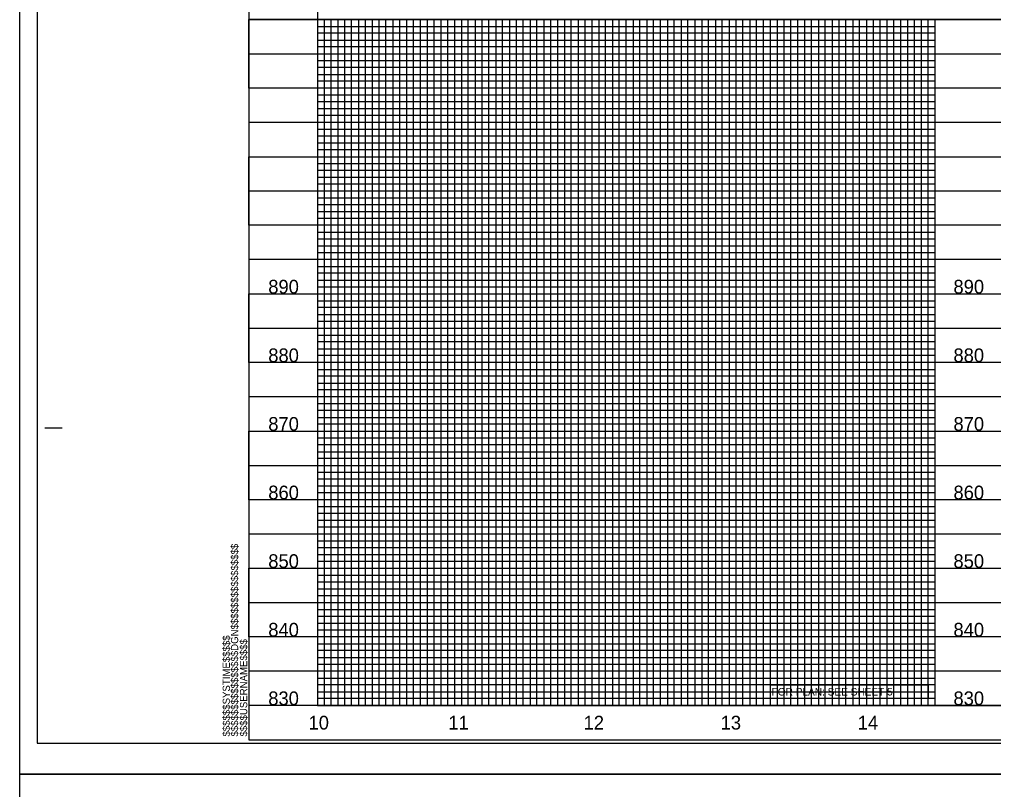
# Model space of a CAD drawing. Extents: x 1967929 to 1975641, y 546296 to 568534.
# Drawn here: x 1969864 to 1970574, y 566323 to 566884 of the extents above; entities that cross this region are included whole.
import ezdxf

# ---------------------------------------------------------------- set-up
doc = ezdxf.new("R2010")
doc.units = 0
for name, color, linetype in [('Exist Vertical Profile Horizontal Axis Label Major', 7, 'Continuous'), ('Exist Vertical Profile Vertical Axis Label', 7, 'Continuous'), ('Old_Level_41', 7, 'Continuous'), ('Old_Level_42', 7, 'Continuous'), ('Prop Grid Mask', 7, 'Continuous'), ('Scratch_Level_3', 7, 'Continuous'), ('Sheet Cutting Line CELL', 7, 'Continuous'), ('Sheet Plot Border Inside CELL', 7, 'Continuous'), ('Sheet Plot Border Outside CELL', 7, 'Continuous'), ('Sheet Profile CELL', 7, 'Continuous'), ('Sheet Profile Grid Major CELL', 7, 'Continuous'), ('Sheet Profile Grid Middle CELL', 7, 'Continuous'), ('Sheet Profile Grid Minor CELL', 7, 'Continuous')]:
    doc.layers.add(name, color=color, linetype=linetype)

msp = doc.modelspace()

# ---------------------------------------------------------------- linework, layer by layer
at = {"layer": 'Old_Level_41'}
msp.add_line((1969882.95, 566586.36), (1969895.45, 566586.36), dxfattribs=at)
at = {"layer": 'Old_Level_42'}
msp.add_line((1970031.45, 566383.86), (1970031.45, 566383.86), dxfattribs=at)
at = {"layer": 'Prop Grid Mask'}
msp.add_lwpolyline([(1970411.53, 566398.9), (1970526.41, 566398.9), (1970526.41, 566388.87), (1970411.53, 566388.87)], close=True, dxfattribs=at)
at = {"layer": 'Scratch_Level_3'}
for points in [[(1970081.45, 566983.86), (1970081.45, 566483.86), (1970581.45, 566483.86), (1970581.45, 566683.86), (1970581.45, 566803.86), (1970581.45, 566983.86)], [(1970081.45, 566883.86), (1970081.45, 566383.86), (1971481.45, 566383.86), (1971481.45, 566883.86)], [(1970081.45, 566883.86), (1970081.45, 566383.86), (1971381.45, 566383.86), (1971381.45, 566883.86)], [(1970081.45, 566883.86), (1970081.45, 566383.86), (1971481.45, 566383.86), (1971481.45, 566883.86)]]:
    msp.add_lwpolyline(points, close=True, dxfattribs=at)
at = {"layer": 'Sheet Cutting Line CELL'}
for p, q in [((1969864.45, 567433.86), (1969864.45, 566333.86)), ((1969864.45, 566333.86), (1971548.45, 566333.86)), ((1969864.45, 566333.86), (1969864.45, 565233.86))]:
    msp.add_line(p, q, dxfattribs=at)
at = {"layer": 'Sheet Plot Border Inside CELL'}
msp.add_lwpolyline([(1969877.45, 566356.31), (1971543.95, 566356.31), (1971543.95, 567411.41), (1969877.45, 567411.41)], close=True, dxfattribs=at)
at = {"layer": 'Sheet Plot Border Outside CELL'}
for points in [[(1969864.45, 566333.86), (1971548.45, 566333.86), (1971548.45, 567433.86), (1969864.45, 567433.86)], [(1969864.45, 565233.86), (1971548.45, 565233.86), (1971548.45, 566333.86), (1969864.45, 566333.86)]]:
    msp.add_lwpolyline(points, close=True, dxfattribs=at)
at = {"layer": 'Sheet Profile CELL'}
for p, q in [((1971531.45, 566883.86), (1970031.45, 566883.86)), ((1971531.45, 566383.86), (1970031.45, 566383.86))]:
    msp.add_line(p, q, dxfattribs=at)
msp.add_lwpolyline([(1971531.45, 567408.86), (1970031.45, 567408.86), (1970031.45, 566358.86), (1971531.45, 566358.86)], close=True, dxfattribs=at)
at = {"layer": 'Sheet Profile Grid Major CELL'}
for points in [[(1971531.45, 566833.86), (1970031.45, 566833.86), (1970031.45, 566883.86), (1971531.45, 566883.86)], [(1970081.45, 566883.86), (1970081.45, 566383.86), (1970131.45, 566383.86), (1970131.45, 566883.86)], [(1970181.45, 566883.86), (1970181.45, 566383.86), (1970231.45, 566383.86), (1970231.45, 566883.86)], [(1970281.45, 566883.86), (1970281.45, 566383.86), (1970331.45, 566383.86), (1970331.45, 566883.86)], [(1970381.45, 566883.86), (1970381.45, 566383.86), (1970431.45, 566383.86), (1970431.45, 566883.86)], [(1970481.45, 566883.86), (1970481.45, 566383.86), (1970531.45, 566383.86), (1970531.45, 566883.86)], [(1971531.45, 566733.86), (1970031.45, 566733.86), (1970031.45, 566783.86), (1971531.45, 566783.86)], [(1971531.45, 566633.86), (1970031.45, 566633.86), (1970031.45, 566683.86), (1971531.45, 566683.86)], [(1971531.45, 566533.86), (1970031.45, 566533.86), (1970031.45, 566583.86), (1971531.45, 566583.86)], [(1971531.45, 566433.86), (1970031.45, 566433.86), (1970031.45, 566483.86), (1971531.45, 566483.86)]]:
    msp.add_lwpolyline(points, dxfattribs=at)
at = {"layer": 'Sheet Profile Grid Middle CELL'}
for points in [[(1970031.45, 566883.86), (1970031.45, 566858.86), (1971531.45, 566858.86)], [(1970106.45, 566383.86), (1970106.45, 566883.86)], [(1970156.45, 566883.86), (1970156.45, 566383.86), (1970206.45, 566383.86), (1970206.45, 566883.86)], [(1970256.45, 566883.86), (1970256.45, 566383.86), (1970306.45, 566383.86), (1970306.45, 566883.86)], [(1970356.45, 566883.86), (1970356.45, 566383.86), (1970406.45, 566383.86), (1970406.45, 566883.86)], [(1970456.45, 566883.86), (1970456.45, 566383.86), (1970506.45, 566383.86), (1970506.45, 566883.86)], [(1971531.45, 566808.86), (1970031.45, 566808.86), (1970031.45, 566758.86), (1971531.45, 566758.86)], [(1971531.45, 566708.86), (1970031.45, 566708.86), (1970031.45, 566658.86), (1971531.45, 566658.86)], [(1971531.45, 566608.86), (1970031.45, 566608.86), (1970031.45, 566558.86), (1971531.45, 566558.86)], [(1971531.45, 566508.86), (1970031.45, 566508.86), (1970031.45, 566458.86), (1971531.45, 566458.86)], [(1971531.45, 566408.86), (1970031.45, 566408.86)]]:
    msp.add_lwpolyline(points, dxfattribs=at)
at = {"layer": 'Sheet Profile Grid Minor CELL'}
for points in [[(1970086.45, 566883.86), (1970086.45, 566383.86), (1970091.45, 566383.86), (1970091.45, 566883.86)], [(1970096.45, 566883.86), (1970096.45, 566383.86), (1970101.45, 566383.86), (1970101.45, 566883.86)], [(1970111.45, 566883.86), (1970111.45, 566383.86), (1970116.45, 566383.86), (1970116.45, 566883.86)], [(1970121.45, 566883.86), (1970121.45, 566383.86), (1970126.45, 566383.86), (1970126.45, 566883.86)], [(1970136.45, 566883.86), (1970136.45, 566383.86), (1970141.45, 566383.86), (1970141.45, 566883.86)], [(1970146.45, 566883.86), (1970146.45, 566383.86), (1970151.45, 566383.86), (1970151.45, 566883.86)], [(1970161.45, 566883.86), (1970161.45, 566383.86), (1970166.45, 566383.86), (1970166.45, 566883.86)], [(1970171.45, 566883.86), (1970171.45, 566383.86), (1970176.45, 566383.86), (1970176.45, 566883.86)], [(1970186.45, 566883.86), (1970186.45, 566383.86), (1970191.45, 566383.86), (1970191.45, 566883.86)], [(1970196.45, 566883.86), (1970196.45, 566383.86), (1970201.45, 566383.86), (1970201.45, 566883.86)], [(1970211.45, 566883.86), (1970211.45, 566383.86), (1970216.45, 566383.86), (1970216.45, 566883.86)], [(1970221.45, 566883.86), (1970221.45, 566383.86), (1970226.45, 566383.86), (1970226.45, 566883.86)], [(1970236.45, 566883.86), (1970236.45, 566383.86), (1970241.45, 566383.86), (1970241.45, 566883.86)], [(1970246.45, 566383.86), (1970251.45, 566383.86), (1970251.45, 566883.86)], [(1970246.45, 566883.86), (1970246.45, 566383.86)], [(1970261.45, 566883.86), (1970261.45, 566383.86), (1970266.45, 566383.86), (1970266.45, 566883.86)], [(1970271.45, 566883.86), (1970271.45, 566383.86), (1970276.45, 566383.86), (1970276.45, 566883.86)], [(1970286.45, 566883.86), (1970286.45, 566383.86), (1970291.45, 566383.86), (1970291.45, 566883.86)], [(1970296.45, 566883.86), (1970296.45, 566383.86), (1970301.45, 566383.86), (1970301.45, 566883.86)], [(1970311.45, 566883.86), (1970311.45, 566383.86), (1970316.45, 566383.86), (1970316.45, 566883.86)], [(1970321.45, 566883.86), (1970321.45, 566383.86), (1970326.45, 566383.86), (1970326.45, 566883.86)], [(1970336.45, 566883.86), (1970336.45, 566383.86), (1970341.45, 566383.86), (1970341.45, 566883.86)], [(1970346.45, 566883.86), (1970346.45, 566383.86), (1970351.45, 566383.86), (1970351.45, 566883.86)], [(1970361.45, 566883.86), (1970361.45, 566383.86), (1970366.45, 566383.86), (1970366.45, 566883.86)], [(1970371.45, 566883.86), (1970371.45, 566383.86), (1970376.45, 566383.86), (1970376.45, 566883.86)], [(1970386.45, 566883.86), (1970386.45, 566383.86), (1970391.45, 566383.86), (1970391.45, 566883.86)], [(1970396.45, 566883.86), (1970396.45, 566383.86), (1970401.45, 566383.86), (1970401.45, 566883.86)], [(1970411.45, 566883.86), (1970411.45, 566383.86), (1970426.45, 566383.86), (1970426.45, 566883.86)], [(1970416.45, 566883.86), (1970416.45, 566383.86), (1970421.45, 566383.86), (1970421.45, 566883.86)], [(1970436.45, 566883.86), (1970436.45, 566383.86), (1970441.45, 566383.86), (1970441.45, 566883.86)], [(1970446.45, 566883.86), (1970446.45, 566383.86), (1970451.45, 566383.86), (1970451.45, 566883.86)], [(1970461.45, 566883.86), (1970461.45, 566383.86), (1970466.45, 566383.86), (1970466.45, 566883.86)], [(1970471.45, 566883.86), (1970471.45, 566383.86), (1970476.45, 566383.86), (1970476.45, 566883.86)], [(1970486.45, 566883.86), (1970486.45, 566383.86), (1970491.45, 566383.86), (1970491.45, 566883.86)], [(1970496.45, 566883.86), (1970496.45, 566383.86), (1970501.45, 566383.86), (1970501.45, 566883.86)], [(1970511.45, 566883.86), (1970511.45, 566383.86), (1970516.45, 566383.86), (1970516.45, 566883.86)], [(1970521.45, 566883.86), (1970521.45, 566383.86), (1970526.45, 566383.86), (1970526.45, 566883.86)], [(1970081.45, 566878.86), (1970531.45, 566878.86)], [(1970531.45, 566873.86), (1970081.45, 566873.86), (1970081.45, 566868.86), (1970531.45, 566868.86)], [(1970531.45, 566863.86), (1970081.45, 566863.86), (1970081.45, 566853.86), (1970531.45, 566853.86)], [(1970531.45, 566848.86), (1970081.45, 566848.86), (1970081.45, 566843.86), (1970531.45, 566843.86)], [(1970531.45, 566838.86), (1970081.45, 566838.86), (1970081.45, 566828.86), (1970531.45, 566828.86)], [(1970531.45, 566823.86), (1970081.45, 566823.86), (1970081.45, 566818.86), (1970531.45, 566818.86)], [(1970531.45, 566813.86), (1970081.45, 566813.86), (1970081.45, 566803.86), (1970531.45, 566803.86)], [(1970531.45, 566798.86), (1970081.45, 566798.86), (1970081.45, 566793.86), (1970531.45, 566793.86)], [(1970531.45, 566788.86), (1970081.45, 566788.86), (1970081.45, 566778.86), (1970531.45, 566778.86)], [(1970531.45, 566773.86), (1970081.45, 566773.86), (1970081.45, 566768.86), (1970531.45, 566768.86)], [(1970531.45, 566763.86), (1970081.45, 566763.86), (1970081.45, 566753.86), (1970531.45, 566753.86)], [(1970531.45, 566748.86), (1970081.45, 566748.86), (1970081.45, 566743.86), (1970531.45, 566743.86)], [(1970531.45, 566738.86), (1970081.45, 566738.86), (1970081.45, 566728.86), (1970531.45, 566728.86)], [(1970531.45, 566723.86), (1970081.45, 566723.86), (1970081.45, 566718.86), (1970531.45, 566718.86)], [(1970531.45, 566713.86), (1970081.45, 566713.86), (1970081.45, 566703.86), (1970531.45, 566703.86)], [(1970531.45, 566698.86), (1970081.45, 566698.86), (1970081.45, 566693.86), (1970531.45, 566693.86)], [(1970531.45, 566688.86), (1970081.45, 566688.86), (1970081.45, 566678.86), (1970531.45, 566678.86)], [(1970531.45, 566673.86), (1970081.45, 566673.86), (1970081.45, 566668.86), (1970531.45, 566668.86)], [(1970531.45, 566663.86), (1970081.45, 566663.86), (1970081.45, 566653.86), (1970531.45, 566653.86)], [(1970531.45, 566648.86), (1970081.45, 566648.86), (1970081.45, 566643.86), (1970531.45, 566643.86)], [(1970531.45, 566638.86), (1970081.45, 566638.86), (1970081.45, 566628.86), (1970531.45, 566628.86)], [(1970531.45, 566623.86), (1970081.45, 566623.86), (1970081.45, 566618.86), (1970531.45, 566618.86)], [(1970531.45, 566613.86), (1970081.45, 566613.86), (1970081.45, 566603.86), (1970531.45, 566603.86)], [(1970531.45, 566598.86), (1970081.45, 566598.86), (1970081.45, 566593.86), (1970531.45, 566593.86)], [(1970531.45, 566588.86), (1970081.45, 566588.86)], [(1970081.45, 566578.86), (1970531.45, 566578.86)], [(1970531.45, 566573.86), (1970081.45, 566573.86), (1970081.45, 566568.86), (1970531.45, 566568.86)], [(1970531.45, 566563.86), (1970081.45, 566563.86)], [(1970081.45, 566553.86), (1970531.45, 566553.86)], [(1970531.45, 566548.86), (1970081.45, 566548.86), (1970081.45, 566543.86), (1970531.45, 566543.86)], [(1970531.45, 566538.86), (1970081.45, 566538.86), (1970081.45, 566528.86), (1970531.45, 566528.86)], [(1970531.45, 566523.86), (1970081.45, 566523.86), (1970081.45, 566518.86), (1970531.45, 566518.86)], [(1970531.45, 566513.86), (1970081.45, 566513.86), (1970081.45, 566503.86), (1970531.45, 566503.86)], [(1970531.45, 566498.86), (1970081.45, 566498.86), (1970081.45, 566493.86), (1970531.45, 566493.86)], [(1970531.45, 566488.86), (1970081.45, 566488.86), (1970081.45, 566478.86), (1970531.45, 566478.86)], [(1970531.45, 566473.86), (1970081.45, 566473.86), (1970081.45, 566468.86), (1970531.45, 566468.86)], [(1970531.45, 566463.86), (1970081.45, 566463.86), (1970081.45, 566453.86), (1970531.45, 566453.86)], [(1970531.45, 566448.86), (1970081.45, 566448.86), (1970081.45, 566443.86), (1970531.45, 566443.86)], [(1970531.45, 566438.86), (1970081.45, 566438.86), (1970081.45, 566428.86), (1970531.45, 566428.86)], [(1970531.45, 566423.86), (1970081.45, 566423.86), (1970081.45, 566418.86), (1970531.45, 566418.86)], [(1970531.45, 566413.86), (1970081.45, 566413.86), (1970081.45, 566403.86), (1970531.45, 566403.86)], [(1970531.45, 566398.86), (1970081.45, 566398.86), (1970081.45, 566393.86), (1970531.45, 566393.86)], [(1970531.45, 566388.86), (1970081.45, 566388.86), (1970081.45, 566383.86), (1971481.45, 566383.86)]]:
    msp.add_lwpolyline(points, dxfattribs=at)

# ---------------------------------------------------------------- texts
at = {"layer": 'Exist Vertical Profile Horizontal Axis Label Major'}
for s, p in [('10', (1970075.03, 566366.36)), ('11', (1970176.87, 566366.36)), ('12', (1970275.42, 566366.36)), ('13', (1970375.26, 566366.36)), ('14', (1970475.1, 566366.36))]:
    msp.add_text(s, height=10, dxfattribs=at).set_placement(p)
at = {"layer": 'Exist Vertical Profile Vertical Axis Label'}
for s, p in [('890', (1970045.7, 566684.11)), ('890', (1970544.88, 566684.11)), ('880', (1970045.7, 566634.11)), ('880', (1970544.88, 566634.11)), ('870', (1970045.7, 566584.11)), ('870', (1970544.88, 566584.11)), ('860', (1970045.7, 566534.11)), ('860', (1970544.88, 566534.11)), ('850', (1970045.7, 566484.11)), ('850', (1970544.88, 566484.11)), ('840', (1970045.7, 566434.11)), ('840', (1970544.88, 566434.11)), ('830', (1970045.7, 566384.11)), ('830', (1970544.88, 566384.11))]:
    msp.add_text(s, height=10, dxfattribs=at).set_placement(p)
at = {"layer": 'Prop Grid Mask'}
msp.add_text('FOR PLAN: SEE SHEET 5', height=5.4932, dxfattribs=at).set_placement((1970412.42, 566391.16))
at = {"layer": 'Sheet Profile CELL'}
for s, p in [('$$$$$$$$$$$$$$$$DGN$$$$$$$$$$$$$$$$', (1970023.8, 566361.23)), ('$$$$$$SYSTIME$$$$$', (1970017.75, 566361.23)), ('$$$$USERNAME$$$$', (1970030.37, 566361.24))]:
    msp.add_text(s, height=5.25, rotation=90, dxfattribs=at).set_placement(p)

doc.saveas('drawing.dxf')
